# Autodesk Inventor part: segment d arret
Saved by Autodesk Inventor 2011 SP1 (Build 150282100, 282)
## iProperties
Created: 2010-12
Part Number: segment d arret
Document SubType Name: Modeling
Designer: eric
Density: 1 g/cm^3
Mass: 0.082009 g
Surface Area: 2.50647 cm^2
Volume: 0.082009 cm^3
Author: eric
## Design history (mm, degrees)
feature "Base1"
node "Solide1"
node "Corps solides"
node "Corps surfaciques"
